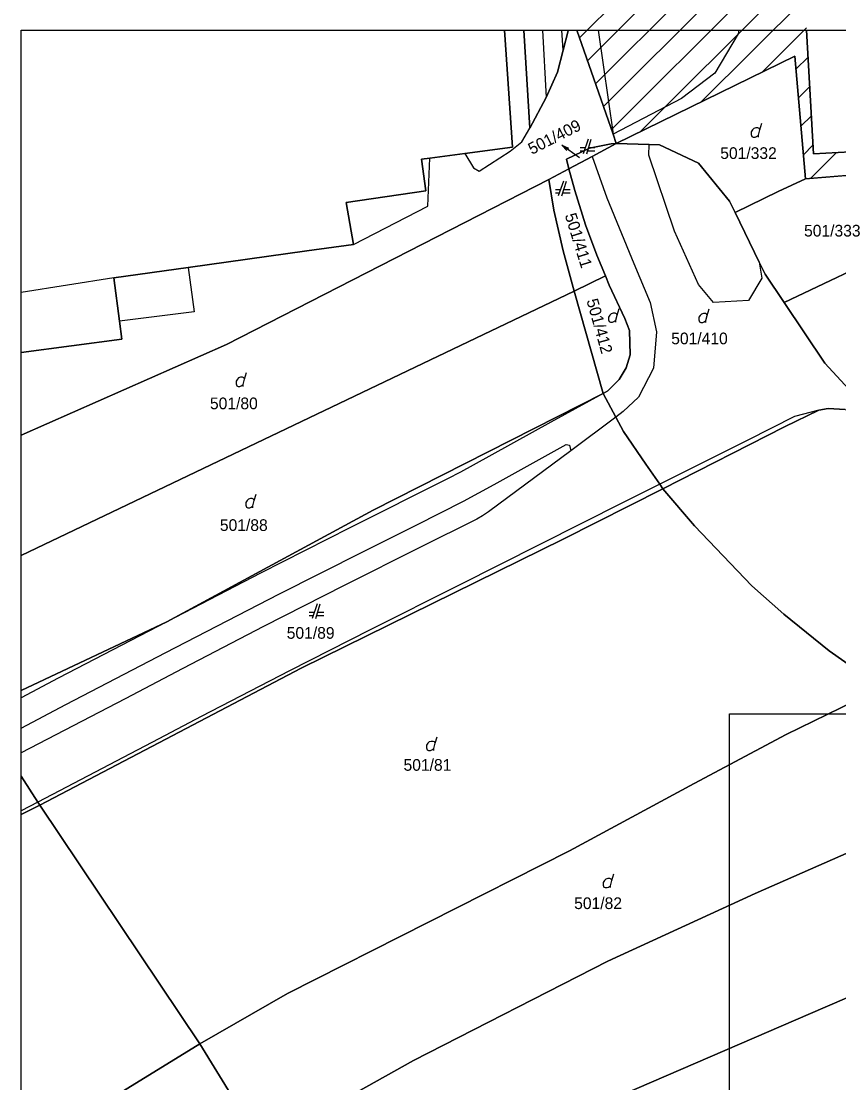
# Model space of a CAD drawing. Extents: x -264309 to -263505, y -1242443 to -1241763.
# Drawn here: x -264307.7 to -264195.9, y -1242101 to -1241955.7 of the extents above; entities that cross this region are included whole.
import ezdxf

# ---------------------------------------------------------------- set-up
doc = ezdxf.new("R2010")
doc.units = 0
for name, color, linetype in [('KN_2019_08_16_KLADPAR', 7, 'Continuous'), ('KN_2019_08_16_ZAPPAR', 7, 'Continuous'), ('RAM_NA_TLAC_10xA4_1-500', 7, 'Continuous'), ('SRAFY_PARCELY', 7, 'Continuous')]:
    doc.layers.add(name, color=color, linetype=linetype)

msp = doc.modelspace()

# ---------------------------------------------------------------- linework, layer by layer
at = {"layer": 'KN_2019_08_16_KLADPAR'}
for p, q in [((-264307.74, -1242001.07), (-264307.74, -1241956.96)), ((-264307.74, -1241956.96), (-264241.62, -1241956.96)), ((-264241.62, -1241956.96), (-264240.52, -1241972.98)), ((-264240.52, -1241972.98), (-264241.62, -1241956.96)), ((-264241.62, -1241956.96), (-264238.96, -1241956.96)), ((-264238.96, -1241956.96), (-264232.88, -1241956.96)), ((-264238.16, -1241970.37), (-264238.96, -1241956.96)), ((-264238.96, -1241956.96), (-264238.16, -1241970.37)), ((-264232.88, -1241957.06), (-264233.57, -1241959.7)), ((-264233.57, -1241959.7), (-264232.88, -1241957.06)), ((-264232.88, -1241956.96), (-264232.88, -1241957.06)), ((-264232.88, -1241957.06), (-264232.88, -1241956.96)), ((-264232.88, -1241956.96), (-264231.72, -1241956.96)), ((-264231.72, -1241956.96), (-264226.76, -1241971.19)), ((-264226.76, -1241971.19), (-264231.72, -1241956.96)), ((-264231.72, -1241956.96), (-264200.28, -1241956.96)), ((-264200.28, -1241956.96), (-264094.27, -1241956.96)), ((-264199.33, -1241973.87), (-264200.28, -1241956.96)), ((-264200.28, -1241956.96), (-264199.33, -1241973.87)), ((-264233.57, -1241959.7), (-264234.36, -1241962.69)), ((-264234.36, -1241962.69), (-264233.57, -1241959.7)), ((-264201.89, -1241960.52), (-264226.31, -1241972.48)), ((-264200.42, -1241977.31), (-264201.89, -1241960.52)), ((-264234.36, -1241962.69), (-264235.89, -1241966.15)), ((-264235.89, -1241966.15), (-264234.36, -1241962.69)), ((-264235.89, -1241966.15), (-264238.16, -1241970.37)), ((-264238.16, -1241970.37), (-264235.89, -1241966.15)), ((-264093.88, -1241968.2), (-264199.33, -1241973.87)), ((-264199.33, -1241973.87), (-264093.88, -1241968.2)), ((-264206.68, -1241970.6), (-264206.41, -1241969.7)), ((-264230.16, -1241971.86), (-264230.86, -1241973.86)), ((-264230.36, -1241973.86), (-264229.76, -1241971.86)), ((-264226.31, -1241972.48), (-264227.01, -1241972.51)), ((-264226.76, -1241971.19), (-264226.31, -1241972.48)), ((-264226.31, -1241972.48), (-264226.76, -1241971.19)), ((-264247.06, -1241973.85), (-264251.82, -1241974.48)), ((-264251.82, -1241974.48), (-264247.06, -1241973.85)), ((-264240.52, -1241972.98), (-264247.06, -1241973.85)), ((-264247.06, -1241973.85), (-264240.52, -1241972.98)), ((-264233.08, -1241973.42), (-264233.77, -1241972.68)), ((-264229.97, -1241973.12), (-264233.15, -1241974.62)), ((-264230.58, -1241973.06), (-264231.26, -1241973.06)), ((-264231.26, -1241973.46), (-264230.72, -1241973.46)), ((-264230.24, -1241973.46), (-264229.26, -1241973.46)), ((-264229.26, -1241973.06), (-264230.12, -1241973.06)), ((-264227.01, -1241972.51), (-264229.97, -1241973.12)), ((-264251.82, -1241974.48), (-264252.96, -1241974.63)), ((-264252.96, -1241974.63), (-264251.82, -1241974.48)), ((-264252.96, -1241974.63), (-264252.36, -1241978.94)), ((-264252.36, -1241978.94), (-264252.96, -1241974.63)), ((-264233.15, -1241974.62), (-264232.8, -1241975.94)), ((-264160.11, -1241973.99), (-264200.42, -1241977.31)), ((-264232.8, -1241975.94), (-264235.54, -1241977.4)), ((-264279.66, -1242000), (-264235.54, -1241977.4)), ((-264235.54, -1241977.4), (-264279.66, -1242000)), ((-264235.54, -1241977.4), (-264234.85, -1241981.6)), ((-264233.55, -1241977.61), (-264234.25, -1241979.61)), ((-264233.75, -1241979.61), (-264233.15, -1241977.61)), ((-264252.36, -1241978.94), (-264263.29, -1241980.54)), ((-264263.29, -1241980.54), (-264252.36, -1241978.94)), ((-264233.97, -1241978.81), (-264234.65, -1241978.81)), ((-264234.65, -1241979.21), (-264234.11, -1241979.21)), ((-264233.63, -1241979.21), (-264232.65, -1241979.21)), ((-264232.65, -1241978.81), (-264233.51, -1241978.81)), ((-264263.29, -1241980.54), (-264262.27, -1241986.28)), ((-264262.27, -1241986.28), (-264263.29, -1241980.54)), ((-264234.85, -1241981.6), (-264233.59, -1241987.17)), ((-264262.27, -1241986.28), (-264268.66, -1241987.17)), ((-264268.66, -1241987.17), (-264262.27, -1241986.28)), ((-264268.66, -1241987.17), (-264284.89, -1241989.43)), ((-264284.89, -1241989.43), (-264268.66, -1241987.17)), ((-264233.59, -1241987.17), (-264232.08, -1241992.67)), ((-264284.89, -1241989.43), (-264295.05, -1241990.85)), ((-264295.05, -1241990.85), (-264284.89, -1241989.43)), ((-264295.05, -1241990.85), (-264294.28, -1241996.79)), ((-264294.28, -1241996.79), (-264295.05, -1241990.85)), ((-264232.08, -1241992.67), (-264307.74, -1242028.86)), ((-264307.74, -1242028.86), (-264232.08, -1241992.67)), ((-264232.08, -1241992.67), (-264228.13, -1242006.68)), ((-264226.19, -1241995.95), (-264225.92, -1241995.05)), ((-264213.86, -1241995.99), (-264213.59, -1241995.09)), ((-264294.28, -1241996.79), (-264293.96, -1241999.25)), ((-264293.96, -1241999.25), (-264294.28, -1241996.79)), ((-264293.96, -1241999.25), (-264307.74, -1242001.07)), ((-264307.74, -1242001.07), (-264293.96, -1241999.25)), ((-264307.74, -1242012.41), (-264279.66, -1242000)), ((-264279.66, -1242000), (-264307.74, -1242012.41)), ((-264307.74, -1242012.41), (-264307.74, -1242001.07)), ((-264277.18, -1242004.73), (-264276.91, -1242003.83)), ((-264259.6, -1242022.67), (-264228.13, -1242006.68)), ((-264228.13, -1242006.68), (-264259.6, -1242022.67)), ((-264228.13, -1242006.68), (-264226.38, -1242009.92)), ((-264226.38, -1242009.92), (-264225.31, -1242011.9)), ((-264307.74, -1242028.86), (-264307.74, -1242012.41)), ((-264225.31, -1242011.9), (-264222.27, -1242016.38)), ((-264222.27, -1242016.38), (-264220.36, -1242019.1)), ((-264275.85, -1242021.35), (-264275.58, -1242020.45)), ((-264219.93, -1242019.72), (-264233.57, -1242026.64)), ((-264220.36, -1242019.1), (-264219.93, -1242019.72)), ((-264287.82, -1242037.94), (-264259.6, -1242022.67)), ((-264259.6, -1242022.67), (-264287.82, -1242037.94)), ((-264233.57, -1242026.64), (-264269.44, -1242044.29)), ((-264307.74, -1242047.34), (-264307.74, -1242028.86)), ((-264267.23, -1242035.47), (-264267.93, -1242037.47)), ((-264267.43, -1242037.47), (-264266.83, -1242035.47)), ((-264267.65, -1242036.67), (-264268.33, -1242036.67)), ((-264268.33, -1242037.07), (-264267.79, -1242037.07)), ((-264267.31, -1242037.07), (-264266.33, -1242037.07)), ((-264266.33, -1242036.67), (-264267.19, -1242036.67)), ((-264307.74, -1242047.34), (-264287.82, -1242037.94)), ((-264287.82, -1242037.94), (-264307.74, -1242047.34)), ((-264269.44, -1242044.29), (-264287.97, -1242054.01)), ((-264307.74, -1242059.09), (-264307.74, -1242047.34)), ((-264251.11, -1242054.57), (-264250.84, -1242053.67)), ((-264287.97, -1242054.01), (-264305.18, -1242063.04)), ((-264305.45, -1242062.62), (-264307.74, -1242059.09)), ((-264307.74, -1242064.3), (-264307.74, -1242059.09)), ((-264307.74, -1242059.09), (-264305.45, -1242062.62)), ((-264305.18, -1242063.04), (-264307.74, -1242064.3)), ((-264307.74, -1242064.3), (-264305.18, -1242063.04)), ((-264305.18, -1242063.04), (-264305.45, -1242062.62)), ((-264305.45, -1242062.62), (-264305.18, -1242063.04)), ((-264305.18, -1242063.04), (-264283.31, -1242095.71)), ((-264307.74, -1242110.73), (-264307.74, -1242064.3)), ((-264226.92, -1242073.34), (-264226.65, -1242072.44)), ((-264307.74, -1242110.73), (-264283.31, -1242095.71)), ((-264283.31, -1242095.71), (-264307.74, -1242110.73)), ((-264283.31, -1242095.71), (-264278.66, -1242103.27))]:
    msp.add_line(p, q, dxfattribs=at)
for points in [[(-264226.31, -1241972.48), (-264201.89, -1241960.52), (-264200.42, -1241977.31), (-264204.15, -1241979.03), (-264210.07, -1241981.92), (-264210.83, -1241980.37), (-264215.08, -1241975.18), (-264220.4, -1241972.67), (-264221.83, -1241972.62)], [(-264232.8, -1241975.94), (-264233.15, -1241974.62), (-264229.97, -1241973.12), (-264227.01, -1241972.51), (-264226.31, -1241972.48), (-264229.61, -1241974.24)], [(-264160.11, -1241973.99), (-264135.89, -1241972), (-264133.98, -1241977.23), (-264193.93, -1242006.68), (-264197.79, -1242002.53), (-264203.35, -1241994.24), (-264187.95, -1241986.93)], [(-264200.42, -1241977.31), (-264160.11, -1241973.99), (-264187.95, -1241986.93), (-264203.35, -1241994.24), (-264205.96, -1241990.34), (-264206.76, -1241988.71), (-264210.07, -1241981.92), (-264204.15, -1241979.03)], [(-264235.54, -1241977.4), (-264232.8, -1241975.94), (-264232, -1241978.9), (-264230.51, -1241983.59), (-264228.99, -1241987.73), (-264227.81, -1241990.58), (-264232.08, -1241992.67), (-264233.59, -1241987.17), (-264234.85, -1241981.6)], [(-264184.63, -1242044.36), (-264189.98, -1242046.97), (-264197.18, -1242041.92), (-264203.38, -1242036.91), (-264207.78, -1242033.03), (-264215.63, -1242024.82), (-264219.93, -1242019.72), (-264203.29, -1242011.27), (-264198.58, -1242008.96), (-264197.33, -1242008.76), (-264194.98, -1242008.87), (-264193.09, -1242009.32), (-264190.87, -1242010.33), (-264189.65, -1242011.32), (-264193.93, -1242006.68), (-264133.98, -1241977.23), (-264118.01, -1242013.33), (-264147.41, -1242027.03), (-264155.75, -1242030.57)], [(-264227.81, -1241990.58), (-264227.27, -1241991.88), (-264225.13, -1241996.43), (-264224.52, -1241998.08), (-264224.43, -1242001.41), (-264224.98, -1242003.16), (-264225.94, -1242004.78), (-264227.49, -1242006.3), (-264228.13, -1242006.68), (-264232.08, -1241992.67)], [(-264215.64, -1242060.08), (-264232.73, -1242069.28), (-264271.31, -1242088.83), (-264283.31, -1242095.71), (-264305.18, -1242063.04), (-264287.97, -1242054.01), (-264269.44, -1242044.29), (-264233.57, -1242026.64), (-264219.93, -1242019.72), (-264215.63, -1242024.82), (-264207.78, -1242033.03), (-264203.38, -1242036.91), (-264197.18, -1242041.92), (-264189.98, -1242046.97), (-264203.07, -1242053.35)], [(-264232.73, -1242069.28), (-264215.64, -1242060.08), (-264203.07, -1242053.35), (-264189.98, -1242046.97), (-264181.27, -1242051.82), (-264173.43, -1242055.54), (-264168.01, -1242057.92), (-264176.29, -1242061.5), (-264207.3, -1242075.14), (-264227.48, -1242084.41), (-264254.05, -1242097.99), (-264274.79, -1242109.56), (-264278.66, -1242103.27), (-264283.31, -1242095.71), (-264271.31, -1242088.83)], [(-264168.01, -1242057.92), (-264161.74, -1242060.05), (-264155.45, -1242062), (-264148.68, -1242063.74), (-264141.87, -1242065.13), (-264136.47, -1242066.18), (-264140.89, -1242068), (-264182.59, -1242084.17), (-264197.75, -1242090.71), (-264231.21, -1242105.15), (-264240.95, -1242110.43), (-264265.78, -1242123.95), (-264268.86, -1242119.03), (-264274.79, -1242109.56), (-264254.05, -1242097.99), (-264227.48, -1242084.41), (-264207.3, -1242075.14), (-264176.29, -1242061.5)], [(-264136.47, -1242066.18), (-264126.66, -1242067.07), (-264113.43, -1242067.44), (-264093.07, -1242066.63), (-264091, -1242071.24), (-264106.54, -1242077.18), (-264118.83, -1242081.48), (-264143.3, -1242090.1), (-264171.23, -1242099.67), (-264195.32, -1242108.83), (-264231.66, -1242125.67), (-264256.42, -1242138.67), (-264258.61, -1242135.22), (-264265.78, -1242123.95), (-264240.95, -1242110.43), (-264231.21, -1242105.15), (-264197.75, -1242090.71), (-264182.59, -1242084.17), (-264140.89, -1242068)]]:
    msp.add_lwpolyline(points, close=True, dxfattribs=at)
for points in [[(-264206.86, -1241971.59), (-264206.86, -1241971.32), (-264206.68, -1241970.6), (-264206.77, -1241970.42), (-264206.95, -1241970.33), (-264207.22, -1241970.33), (-264207.49, -1241970.42), (-264207.67, -1241970.6), (-264207.85, -1241970.87), (-264207.85, -1241971.23), (-264207.76, -1241971.5), (-264207.58, -1241971.59), (-264207.31, -1241971.59), (-264207.13, -1241971.5), (-264206.86, -1241971.32)], [(-264194.98, -1242008.87), (-264197.33, -1242008.76), (-264198.58, -1242008.96), (-264203.29, -1242011.27), (-264219.93, -1242019.72), (-264220.36, -1242019.1), (-264222.27, -1242016.38), (-264225.31, -1242011.9), (-264226.38, -1242009.92), (-264228.13, -1242006.68), (-264227.49, -1242006.3), (-264225.94, -1242004.78), (-264224.98, -1242003.16), (-264224.43, -1242001.41), (-264224.52, -1241998.08), (-264225.13, -1241996.43), (-264227.27, -1241991.88), (-264227.81, -1241990.58), (-264228.99, -1241987.73), (-264230.51, -1241983.59), (-264232, -1241978.9), (-264232.8, -1241975.94), (-264229.61, -1241974.24), (-264226.31, -1241972.48), (-264221.83, -1241972.62), (-264220.4, -1241972.67), (-264215.08, -1241975.18), (-264210.83, -1241980.37), (-264210.07, -1241981.92), (-264206.76, -1241988.71), (-264205.96, -1241990.34), (-264203.35, -1241994.24), (-264197.79, -1242002.53), (-264193.93, -1242006.68)], [(-264231.33, -1241974.42), (-264233.77, -1241972.68), (-264232.84, -1241973.1)], [(-264226.37, -1241996.94), (-264226.37, -1241996.67), (-264226.19, -1241995.95), (-264226.28, -1241995.77), (-264226.46, -1241995.68), (-264226.73, -1241995.68), (-264227, -1241995.77), (-264227.18, -1241995.95), (-264227.36, -1241996.22), (-264227.36, -1241996.58), (-264227.27, -1241996.85), (-264227.09, -1241996.94), (-264226.82, -1241996.94), (-264226.64, -1241996.85), (-264226.37, -1241996.67)], [(-264214.04, -1241996.98), (-264214.04, -1241996.71), (-264213.86, -1241995.99), (-264213.95, -1241995.81), (-264214.13, -1241995.72), (-264214.4, -1241995.72), (-264214.67, -1241995.81), (-264214.85, -1241995.99), (-264215.03, -1241996.26), (-264215.03, -1241996.62), (-264214.94, -1241996.89), (-264214.76, -1241996.98), (-264214.49, -1241996.98), (-264214.31, -1241996.89), (-264214.04, -1241996.71)], [(-264277.36, -1242005.72), (-264277.36, -1242005.45), (-264277.18, -1242004.73), (-264277.27, -1242004.55), (-264277.45, -1242004.46), (-264277.72, -1242004.46), (-264277.99, -1242004.55), (-264278.17, -1242004.73), (-264278.35, -1242005), (-264278.35, -1242005.36), (-264278.26, -1242005.63), (-264278.08, -1242005.72), (-264277.81, -1242005.72), (-264277.63, -1242005.63), (-264277.36, -1242005.45)], [(-264276.03, -1242022.34), (-264276.03, -1242022.07), (-264275.85, -1242021.35), (-264275.94, -1242021.17), (-264276.12, -1242021.08), (-264276.39, -1242021.08), (-264276.66, -1242021.17), (-264276.84, -1242021.35), (-264277.02, -1242021.62), (-264277.02, -1242021.98), (-264276.93, -1242022.25), (-264276.75, -1242022.34), (-264276.48, -1242022.34), (-264276.3, -1242022.25), (-264276.03, -1242022.07)], [(-264251.29, -1242055.56), (-264251.29, -1242055.29), (-264251.11, -1242054.57), (-264251.2, -1242054.39), (-264251.38, -1242054.3), (-264251.65, -1242054.3), (-264251.92, -1242054.39), (-264252.1, -1242054.57), (-264252.28, -1242054.84), (-264252.28, -1242055.2), (-264252.19, -1242055.47), (-264252.01, -1242055.56), (-264251.74, -1242055.56), (-264251.56, -1242055.47), (-264251.29, -1242055.29)], [(-264227.1, -1242074.33), (-264227.1, -1242074.06), (-264226.92, -1242073.34), (-264227.01, -1242073.16), (-264227.19, -1242073.07), (-264227.46, -1242073.07), (-264227.73, -1242073.16), (-264227.91, -1242073.34), (-264228.09, -1242073.61), (-264228.09, -1242073.97), (-264228, -1242074.24), (-264227.82, -1242074.33), (-264227.55, -1242074.33), (-264227.37, -1242074.24), (-264227.1, -1242074.06)]]:
    msp.add_lwpolyline(points, dxfattribs=at)
at = {"layer": 'KN_2019_08_16_ZAPPAR'}
for p, q in [((-264236.4, -1241956.96), (-264235.89, -1241966.15)), ((-264233.57, -1241959.7), (-264233.79, -1241956.96)), ((-264228.78, -1241956.96), (-264226.76, -1241971.19)), ((-264245.1, -1241976.23), (-264240.82, -1241973.5)), ((-264252.12, -1241981.04), (-264251.82, -1241974.48)), ((-264262.27, -1241986.28), (-264252.12, -1241981.04)), ((-264215.06, -1241991.78), (-264218.33, -1241984.48)), ((-264284.89, -1241989.43), (-264284.06, -1241995.49)), ((-264295.05, -1241990.85), (-264307.74, -1241992.84)), ((-264284.06, -1241995.49), (-264294.28, -1241996.79)), ((-264220.8, -1241998.26), (-264221.21, -1242003.23)), ((-264226.38, -1242009.92), (-264232.54, -1242014.52)), ((-264208.31, -1242013.08), (-264215.96, -1242016.91)), ((-264215.96, -1242016.91), (-264220.36, -1242019.1)), ((-264249.4, -1242018.38), (-264262.79, -1242025.08)), ((-264287.95, -1242042.15), (-264272.51, -1242034.15)), ((-264287.82, -1242037.94), (-264302.69, -1242045.66)), ((-264274.6, -1242038.58), (-264285.65, -1242044.33)), ((-264259.98, -1242039.04), (-264271.05, -1242044.65)), ((-264302.69, -1242045.66), (-264307.74, -1242048.33)), ((-264305.45, -1242062.62), (-264307.74, -1242063.83))]:
    msp.add_line(p, q, dxfattribs=at)
for points in [[(-264209.55, -1241956.96), (-264209.65, -1241957.44), (-264212.85, -1241962.85), (-264217.41, -1241966.31), (-264226.76, -1241971.19)], [(-264240.82, -1241973.5), (-264239.24, -1241972.23), (-264238.16, -1241970.37)], [(-264247.06, -1241973.85), (-264245.87, -1241975.78), (-264245.1, -1241976.23)], [(-264218.33, -1241984.48), (-264221.87, -1241974.06), (-264221.83, -1241972.62)], [(-264229.61, -1241974.24), (-264227.62, -1241979.92), (-264223.92, -1241988.87), (-264221.67, -1241994.24), (-264220.8, -1241998.26)], [(-264206.76, -1241988.71), (-264206.39, -1241990.88), (-264208.22, -1241993.97), (-264213.02, -1241994.23), (-264215.06, -1241991.78)], [(-264221.21, -1242003.23), (-264223.28, -1242007.17), (-264225.37, -1242009.17), (-264226.38, -1242009.92)], [(-264228.13, -1242006.68), (-264235.29, -1242010.62), (-264245.88, -1242016.49), (-264247.62, -1242017.47), (-264249.4, -1242018.38)], [(-264198.58, -1242008.96), (-264201.91, -1242009.85), (-264208.31, -1242013.08)], [(-264272.51, -1242034.15), (-264261.01, -1242028.36), (-264253.62, -1242024.66), (-264247.22, -1242021.42), (-264243.04, -1242019.16), (-264233.18, -1242013.67), (-264232.74, -1242013.76), (-264232.54, -1242014.52), (-264243.79, -1242022.89), (-264244.64, -1242023.45), (-264245.42, -1242023.89), (-264253.19, -1242027.76), (-264263.54, -1242032.99), (-264274.6, -1242038.58)], [(-264220.36, -1242019.1), (-264225.39, -1242021.61), (-264236.76, -1242027.35), (-264247.83, -1242032.91), (-264259.98, -1242039.04)], [(-264262.79, -1242025.08), (-264275, -1242031.26), (-264287.82, -1242037.94)], [(-264307.74, -1242052.49), (-264301.62, -1242049.26), (-264287.95, -1242042.15)], [(-264285.65, -1242044.33), (-264293.54, -1242048.46), (-264305.4, -1242054.64), (-264307.74, -1242055.87)], [(-264271.05, -1242044.65), (-264283.12, -1242050.91), (-264288.91, -1242053.94), (-264301.56, -1242060.58), (-264305.45, -1242062.62)]]:
    msp.add_lwpolyline(points, dxfattribs=at)
at = {"layer": 'RAM_NA_TLAC_10xA4_1-500'}
msp.add_lwpolyline([(-264210.83, -1242050.54), (-264105.83, -1242050.54), (-264000.83, -1242050.54), (-263895.83, -1242050.54), (-263790.83, -1242050.54), (-263685.83, -1242050.54), (-263685.83, -1242199.04), (-263685.83, -1242347.54), (-263790.83, -1242347.54), (-263895.83, -1242347.54), (-264000.83, -1242347.54), (-264105.83, -1242347.54), (-264210.83, -1242347.54), (-264210.83, -1242199.04)], close=True, dxfattribs=at)
at = {"layer": 'SRAFY_PARCELY'}
for p, q in [((-264231.36, -1241957.98), (-264205.84, -1241932.47)), ((-264230.27, -1241961.13), (-264204.03, -1241934.9)), ((-264229.17, -1241964.28), (-264202.58, -1241937.69)), ((-264228.07, -1241967.42), (-264201.2, -1241940.55)), ((-264226.98, -1241970.57), (-264200.97, -1241944.57)), ((-264223.05, -1241970.88), (-264200.75, -1241948.58)), ((-264214.73, -1241966.81), (-264200.52, -1241952.6)), ((-264206.41, -1241962.74), (-264200.3, -1241956.62)), ((-264201.73, -1241962.3), (-264200.07, -1241960.64)), ((-264201.39, -1241966.2), (-264199.85, -1241964.65)), ((-264201.05, -1241970.1), (-264199.62, -1241968.67)), ((-264200.71, -1241974), (-264199.4, -1241972.69)), ((-264199.72, -1241977.25), (-264196.17, -1241973.7))]:
    msp.add_line(p, q, dxfattribs=at)

# ---------------------------------------------------------------- texts
at = {"layer": 'KN_2019_08_16_KLADPAR'}
for s, rotation, p in [('501/409', 26.9863, (-264237.87, -1241974.03)), ('501/411', 287.1664, (-264233.38, -1241982.27)), ('501/412', 285.6768, (-264230.41, -1241993.95))]:
    msp.add_text(s, height=1.6, rotation=rotation, dxfattribs=at).set_placement(p)
for s, p in [('501/332', (-264212.09, -1241974.58)), ('501/333', (-264200.62, -1241985.2)), ('501/410', (-264218.8, -1241999.95)), ('501/80', (-264281.92, -1242008.84)), ('501/88', (-264280.56, -1242025.5)), ('501/89', (-264271.41, -1242040.26)), ('501/81', (-264255.43, -1242058.33)), ('501/82', (-264232.08, -1242077.26))]:
    msp.add_text(s, height=1.6, dxfattribs=at).set_placement(p)

doc.saveas('drawing.dxf')
